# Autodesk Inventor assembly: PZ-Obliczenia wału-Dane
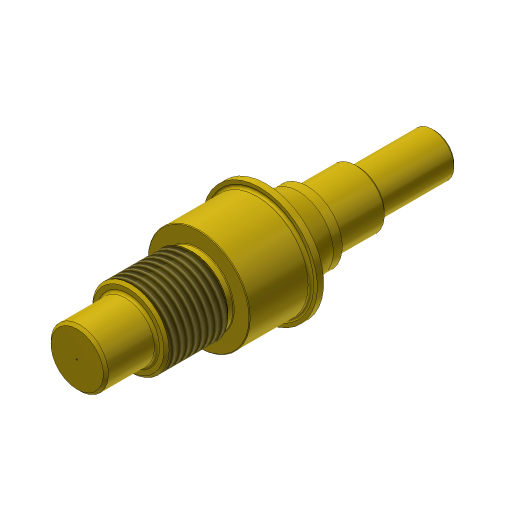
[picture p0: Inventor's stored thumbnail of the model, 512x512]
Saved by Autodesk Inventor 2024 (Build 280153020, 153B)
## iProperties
Company: ATC
Created: 2023-03
Part Number: PZ-Obliczenia wału-Dane
Document SubType Name: Assembly
Designer: Andrzej Jaskulski
Checked By: A.J.
Engr Approved By: Andrzej Jaskulski
Mfg Approved By: Andrzej Jaskulski
Authority: A.J.
Title: A.J.: Kurs R2024-MEP
Author: Andrzej Jaskulski
Revision Number: 1/24
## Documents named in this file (2)
- C:\Users\AndJas\Documents\R2024-MEP\Obszar roboczy\PZ\PZ-Obliczenia wału-Dane.iam
- C:\Users\AndJas\Documents\R2024-MEP\Obszar roboczy\PZ\PZ-Obliczenia wału-Dane\Design Accelerator\Wał1.iam
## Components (1 placed, 1 different names)
1. Wał:1 [sub-assembly] — Zestawiający:1, Równoległy:1, Kąt:1
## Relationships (3: Mate 1, Flush 1, Angle 1)
- Zestawiający:1 [Mate]: Wał:1
- Równoległy:1 [Flush]: Wał:1
- Kąt:1 [Angle]: Wał:1
